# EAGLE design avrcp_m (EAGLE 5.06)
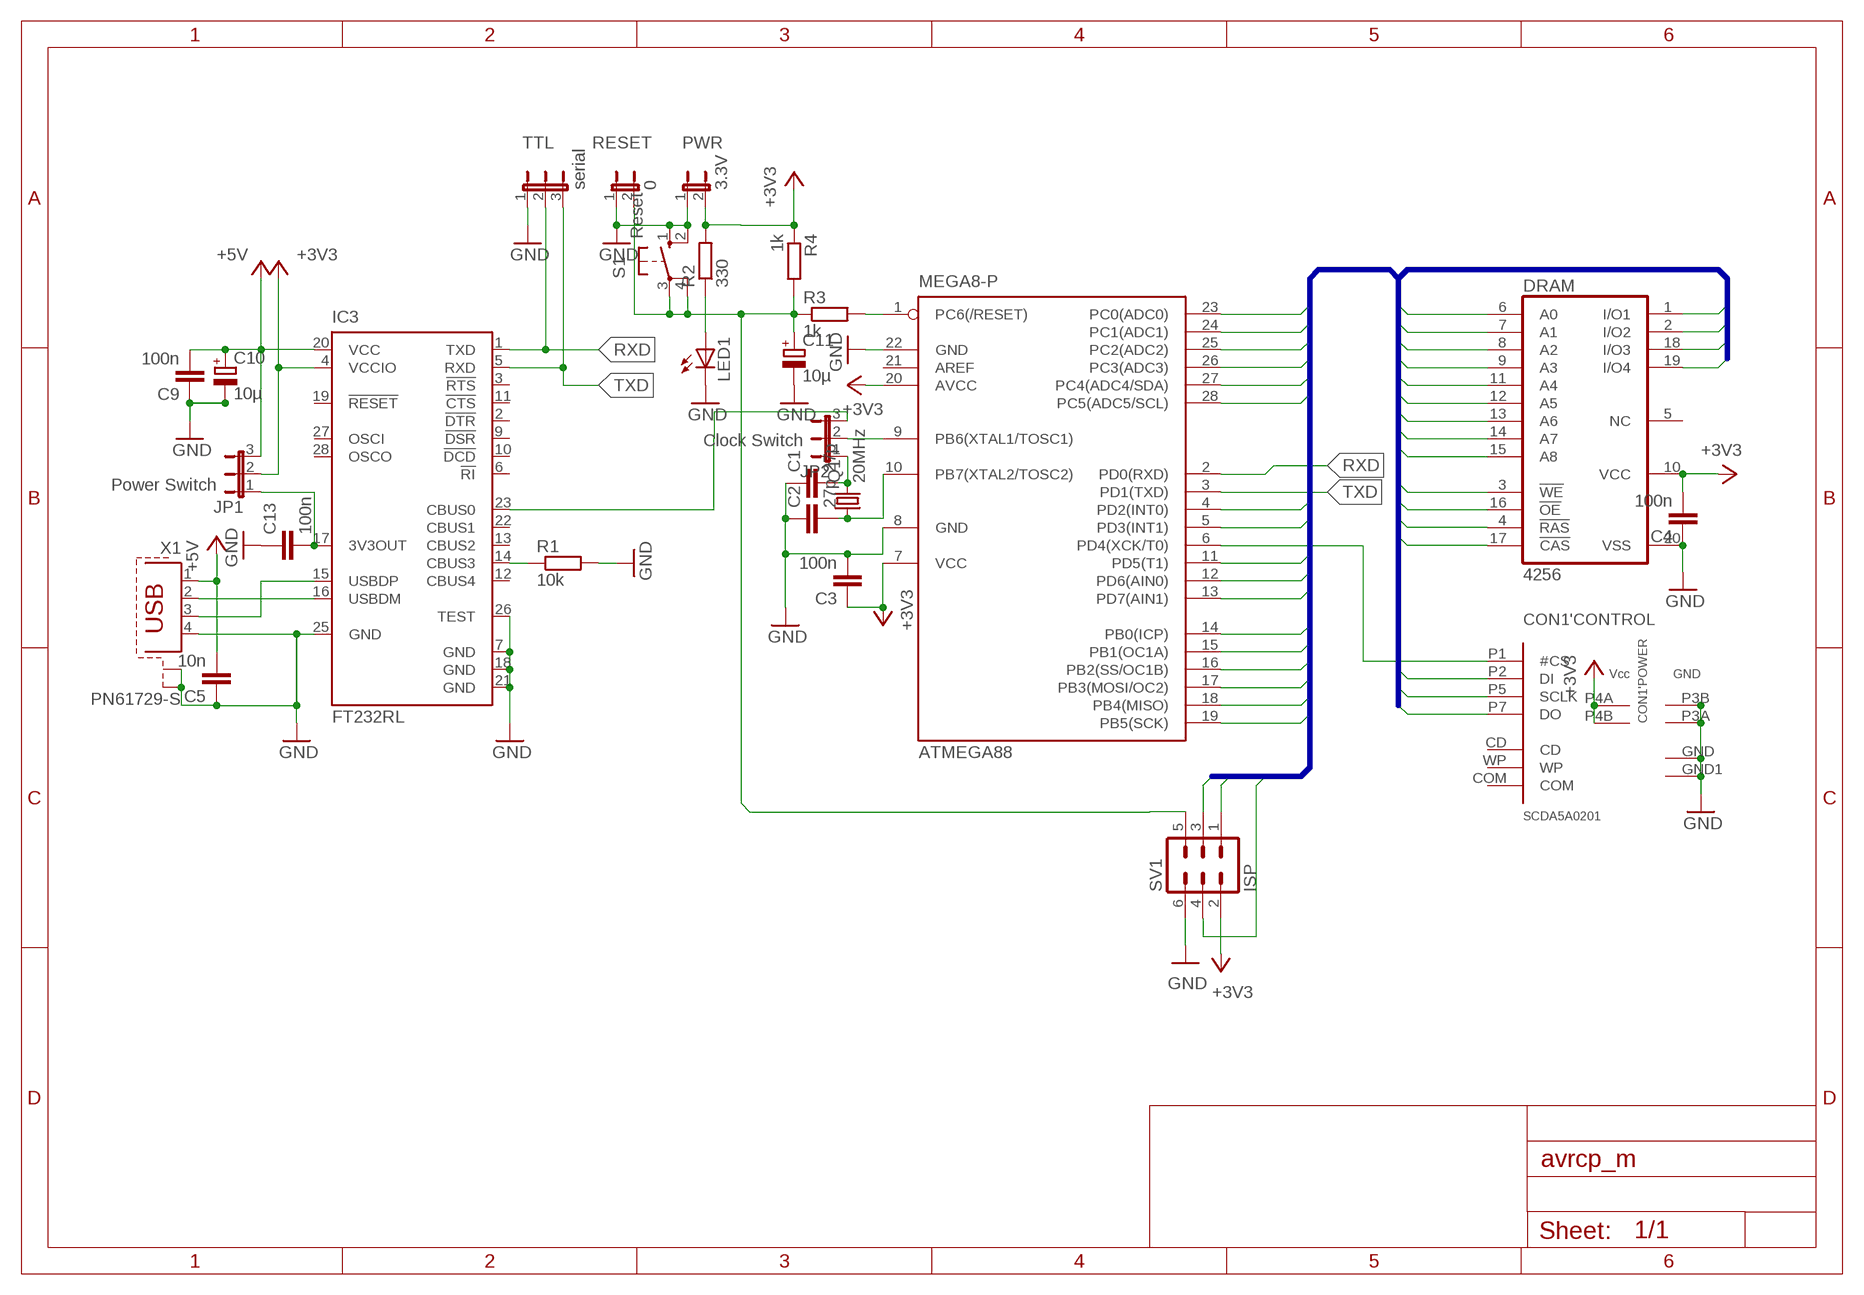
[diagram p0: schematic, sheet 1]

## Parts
ATMEGA88  MEGA8-P  [DIL28-3]
C1  27p  C-EU025-024X044  [C025-024X044]
C2  27p  C-EU025-024X044  [C025-024X044]
C3  100n  C-EU025-024X044  [C025-024X044]
C4  100n  C-EU025-024X044  [C025-024X044]
C5  10n  C-EU025-024X044  [C025-024X044]
C9  100n  C-EU025-024X044  [C025-024X044]
C10  10µ  CPOL-EUE2-5  [E2-5]
C11  10µ  CPOL-EUE2.5-5  [E2,5-5]
C13  100n  C-EU025-024X044  [C025-024X044]
CON1  SCDA5A0201  [SCDA5A0201]
DRAM  4256  514256ALP  [DIL20]
IC3  FT232RL  [SSOP28]
JP1  Power Switch  JP2E  [JP2]
JP2  Clock Switch  JP2E  [JP2]
LED1  LED3MM  [LED3MM]
PWR  3.3V  JP1E  [JP1]
Q1  20MHz  CRYSTALHC49U-V  [HC49U-V]
R1  10k  R-EU_0207/7  [0207/7]
R2  330  R-EU_0207/7  [0207/7]
R3  1k  R-EU_0207/7  [0207/7]
R4  1k  R-EU_0207/7  [0207/7]
RESET  0  JP1E  [JP1]
S1  Reset  10-XX  [B3F-10XX]
SV1  ISP  ML6  [ML6]
TTL  serial  JP2E  [JP2]
X1  PN61729-S  [PN61729-S]

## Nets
+3V3: ATMEGA88.7(VCC) ATMEGA88.20(AVCC) C3.1 C4.2 CON1.P4A('POWER:VCC) CON1.P4B('POWER:VCC1) DRAM.10(VCC) IC3.4(VCCIO) JP1.2 PWR.2 R2.2 R4.1 SV1.2
+5V: C5.2 C9.2 C10.+ IC3.20(VCC) JP1.3 X1.1
A0: ATMEGA88.18(PB4(MISO)) CON1.P7('CONTROL:DO) DRAM.6(A0) SV1.1
A1: ATMEGA88.17(PB3(MOSI/OC2)) CON1.P2('CONTROL:DI) DRAM.7(A1) SV1.4
A2: ATMEGA88.16(PB2(SS/OC1B)) DRAM.8(A2)
A3: ATMEGA88.15(PB1(OC1A)) DRAM.9(A3)
A4: ATMEGA88.14(PB0(ICP)) DRAM.11(A4)
A5: ATMEGA88.11(PD5(T1)) DRAM.12(A5)
A6: ATMEGA88.12(PD6(AIN0)) DRAM.13(A6)
A7: ATMEGA88.13(PD7(AIN1)) DRAM.14(A7)
A8: ATMEGA88.5(PD3(INT1)) DRAM.15(A8)
CAS: ATMEGA88.28(PC5(ADC5/SCL)) DRAM.17(!CAS)
CS: ATMEGA88.6(PD4(XCK/T0)) CON1.P1('CONTROL:#CS)
GND: ATMEGA88.8(GND) ATMEGA88.22(GND) C1.1 C2.1 C3.2 C4.1 C5.1 C9.1 C10.- C11.- C13.1 CON1.GND1('POWER:GND) CON1.GND('POWER:GND) CON1.P3A('POWER:GND) CON1.P3B('POWER:GND) DRAM.20(VSS) IC3.7(GND) IC3.18(GND) IC3.21(GND) IC3.25(GND) IC3.26(TEST) LED1.K(C) PWR.1 R1.2 RESET.1 S1.1(S) S1.2(S1) SV1.6 TTL.1 X1.4 X1.S1 X1.S2
IO1: ATMEGA88.23(PC0(ADC0)) DRAM.1(I/O1)
IO2: ATMEGA88.25(PC2(ADC2)) DRAM.2(I/O2)
IO3: ATMEGA88.27(PC4(ADC4/SDA)) DRAM.18(I/O3)
IO4: ATMEGA88.26(PC3(ADC3)) DRAM.19(I/O4)
N$1: IC3.14(CBUS3) R1.1
N$2: C13.2 IC3.17(3V3OUT) JP1.1
N$4: ATMEGA88.9(PB6(XTAL1/TOSC1)) JP2.2
N$5: ATMEGA88.10(PB7(XTAL2/TOSC2)) C2.2 Q1.1
N$6: C1.2 JP2.1 Q1.2
N$7: LED1.A R2.1
N$8: IC3.23(CBUS0) JP2.3
N$9: IC3.16(USBDM) X1.2
N$10: IC3.15(USBDP) X1.3
N$11: C11.+ R3.1 R4.2 RESET.2 S1.3(P) S1.4(P1) SV1.5
N$12: ATMEGA88.1(PC6(/RESET)) R3.2
OE: ATMEGA88.4(PD2(INT0)) DRAM.16(!OE)
RAS: ATMEGA88.19(PB5(SCK)) CON1.P5('CONTROL:SCLK) DRAM.4(!RAS) SV1.3
RXD: ATMEGA88.2(PD0(RXD)) IC3.1(TXD) TTL.2
TXD: ATMEGA88.3(PD1(TXD)) IC3.5(RXD) TTL.3
WE: ATMEGA88.24(PC1(ADC1)) DRAM.3(!WE)
Unconnected: ATMEGA88.21(AREF) CON1.CD('CONTROL:CD) CON1.COM('CONTROL:COM) CON1.WP('CONTROL:WP) DRAM.5(NC) IC3.2(!DTR) IC3.3(!RTS) IC3.6(!RI) IC3.9(!DSR) IC3.10(!DCD) IC3.11(!CTS) IC3.12(CBUS4) IC3.13(CBUS2) IC3.19(!RESET) IC3.22(CBUS1) IC3.27(OSCI) IC3.28(OSCO)

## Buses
A[0..8],WE,OE,RAS,CAS,IO[1..4]

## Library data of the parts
ATMEGA88 = atmel:MEGA8-P: MICROCONTROLLER 8 Kbytes FLASH, 1 kbytes SRAM, 512 bytes EEPROM, USART, 4-channel 10 bit ADC, 2-channel 8 bit ADC Pin compatible with Atmega48, ATMega88, ATMega168 Source: avr.lbr
C1-C5 C9 C13 = rcl:C-EU: CAPACITOR, European symbol
C10 C11 = rcl:CPOL-EU: POLARIZED CAPACITOR, European symbol
CON1 = SCDA5A0201:SCDA5A0201: ALPS Connector for SDMemory Card SD-CARD SCDA5A0201 SPI -MODE
DRAM = memory-hitachi:514256ALP: MEMORY
IC3 = ftdichip:FT232R: Source: http://www.ftdichip.com/Documents/DataSheets/DS_FT232R_v104.pdf
JP1 JP2 TTL = jumper:JP2E: JUMPER
LED1 = led:LED: LED
PWR RESET = jumper:JP1E: JUMPER
Q1 = crystal:CRYSTAL: CRYSTAL
R1-R4 = rcl:R-EU_: RESISTOR, European symbol
S1 = switch-omron:10-XX: OMRON SWITCH
SV1 = con-harting-ml:ML6: HARTING
X1 = con-berg:PN61729-S: BERG USB connector

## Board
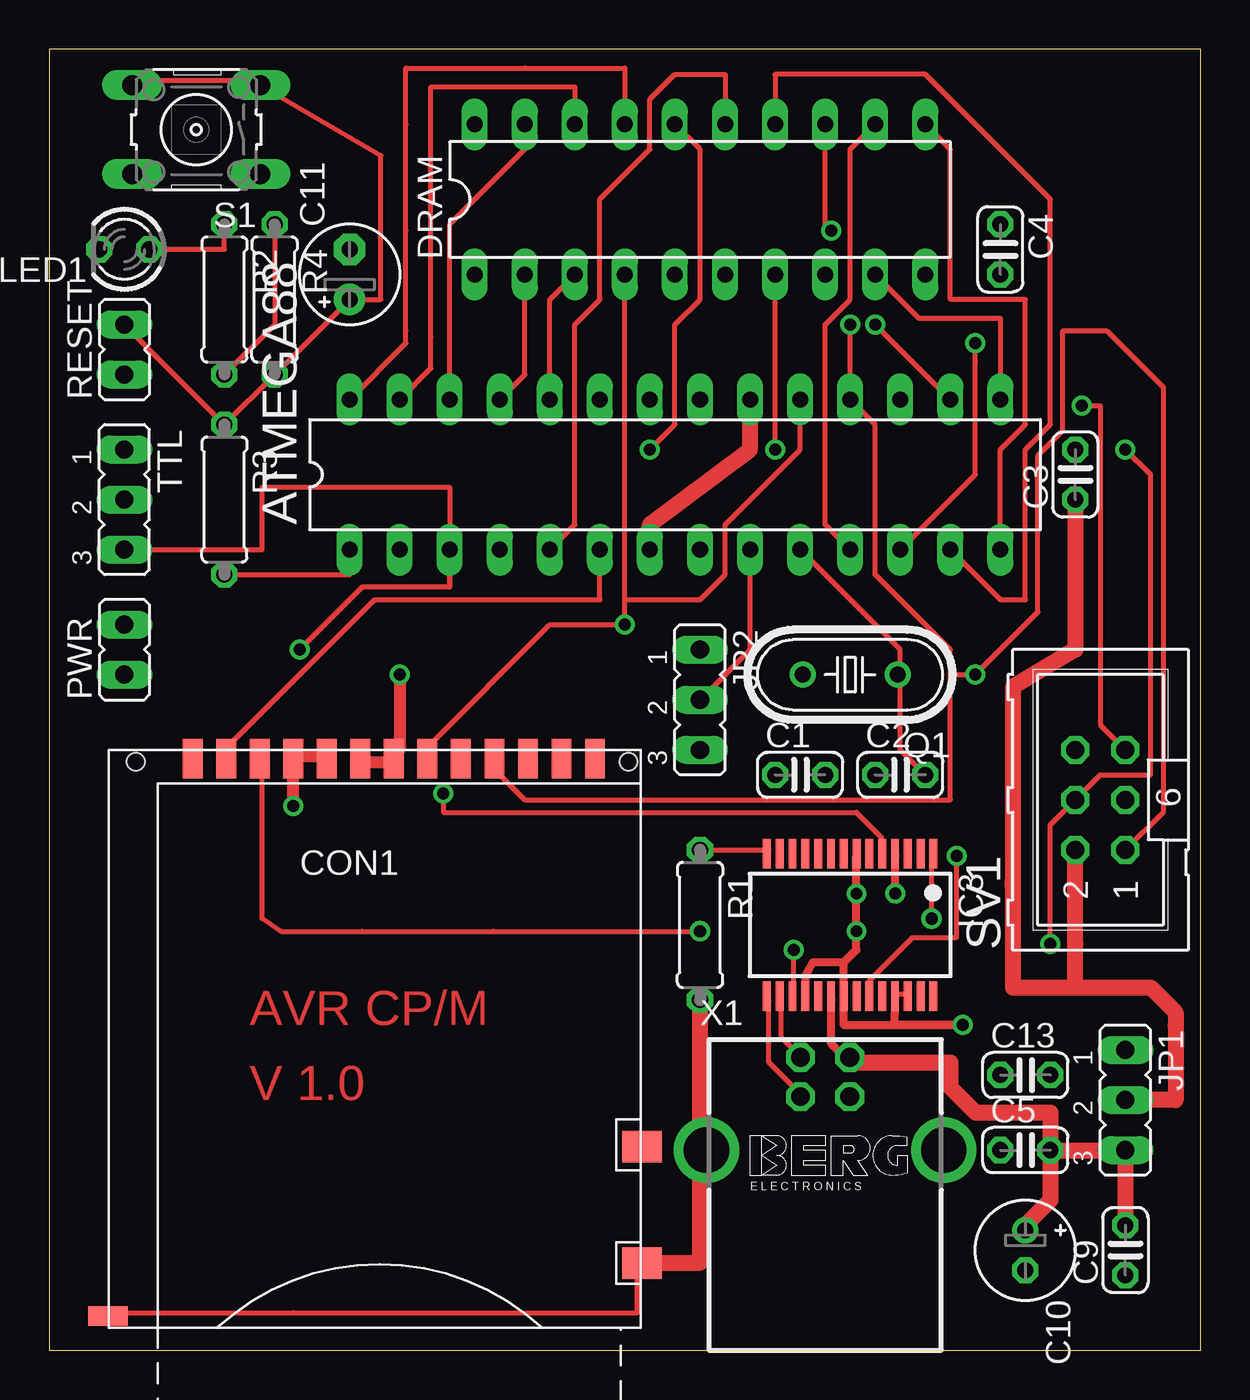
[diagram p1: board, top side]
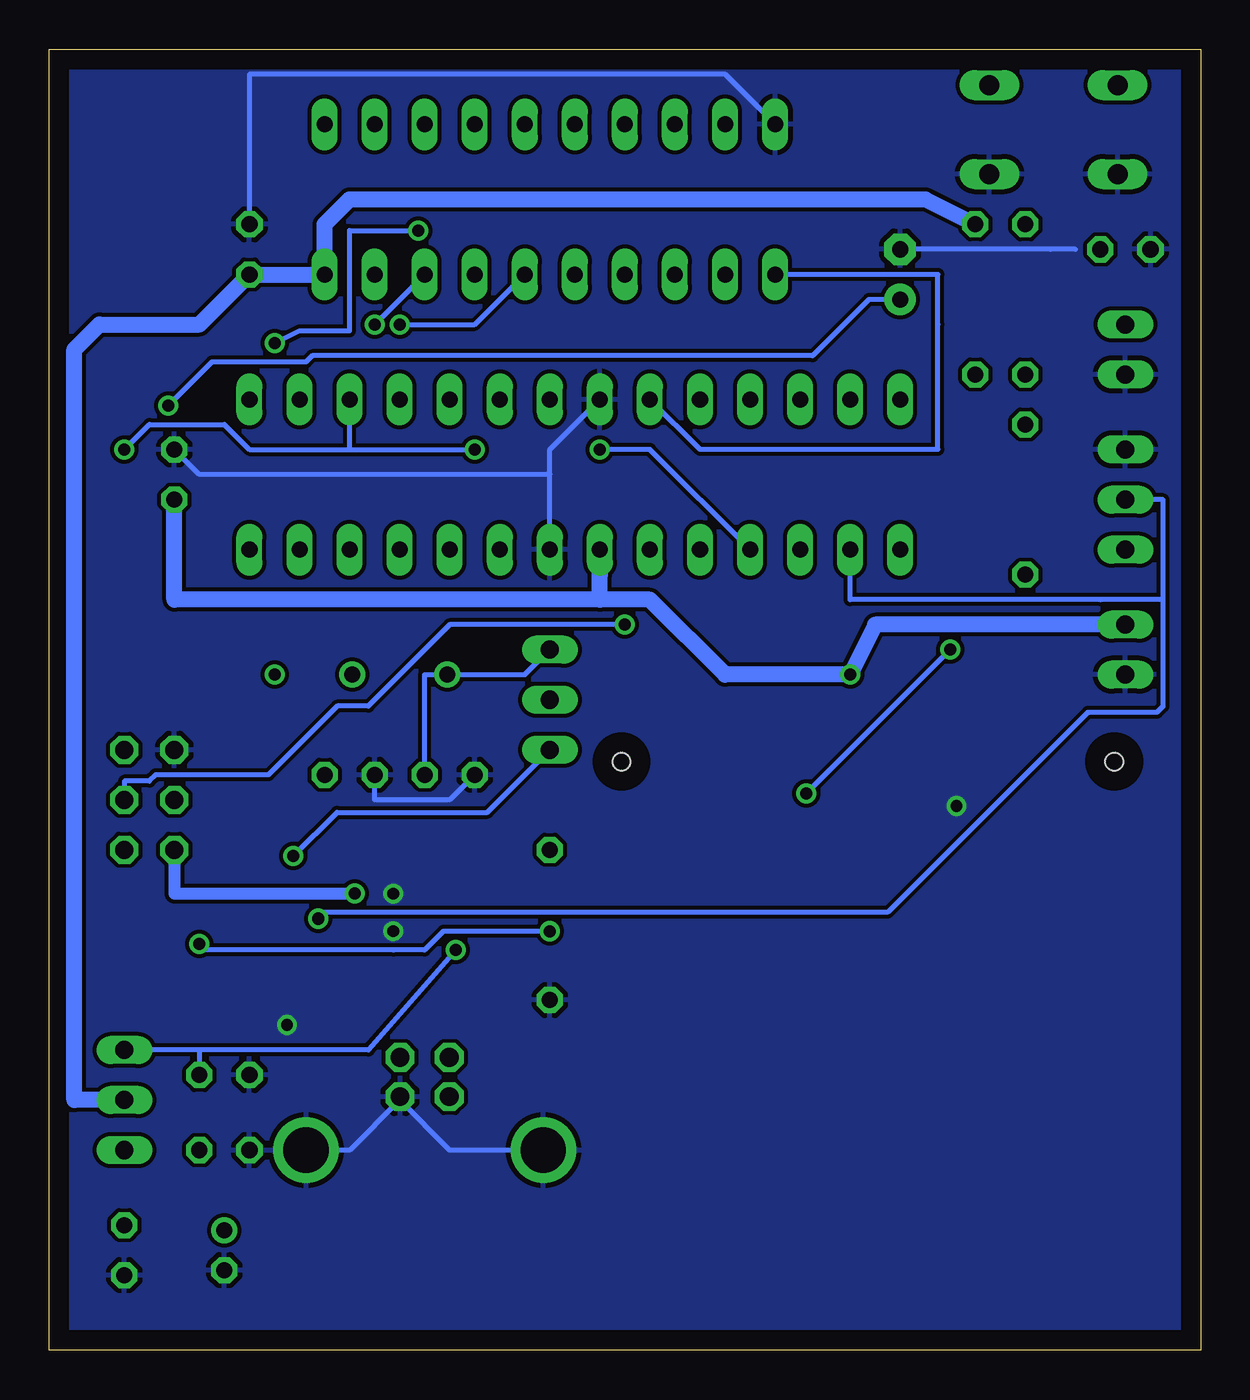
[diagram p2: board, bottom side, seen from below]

Size 58.42 x 66.04 mm. Coordinates in mm from the lower left corner, seen from the top.
Outline: 58.42,66.04 0,66.03 0,0 58.42,0 58.42,66.04
Copper layers (1*16): Top 0.035mm / dielectric 1.5mm / Bottom 0.035mm
Design rules "default": minimum track width 10mil, minimum drill 24mil, track to track 8mil, track to pad 8mil, pad to pad 8mil, via to via 8mil, smd to smd 8mil, copper to edge 40mil, drill to drill 8mil, minimum pad ring 10mil, minimum via ring 8mil, stop-mask expansion 4mil, vias tented up to drill 0mil, thermal gap 10mil

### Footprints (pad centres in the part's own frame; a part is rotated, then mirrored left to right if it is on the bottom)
DIL28-3 = drill 0.813 long: 1 -16.51,-3.81; 2 -13.97,-3.81; 3 -11.43,-3.81; 4 -8.89,-3.81; 5 -6.35,-3.81; 6 -3.81,-3.81; 7 -1.27,-3.81; 8 1.27,-3.81; 9 3.81,-3.81; 10 6.35,-3.81; 11 8.89,-3.81; 12 11.43,-3.81; 13 13.97,-3.81; 14 16.51,-3.81; 15 16.51,3.81; 16 13.97,3.81; 17 11.43,3.81; 18 8.89,3.81; 19 6.35,3.81; 20 3.81,3.81; 21 1.27,3.81; 22 -1.27,3.81; 23 -3.81,3.81; 24 -6.35,3.81; 25 -8.89,3.81; 26 -11.43,3.81; 27 -13.97,3.81; 28 -16.51,3.81
C025-024X044 = drill 0.813 octagon: 1 -1.27,0; 2 1.27,0
E2-5 = drill 0.813 pad 1.27 round: + -1.016,0 | drill 0.813 pad 1.27 octagon: - 1.016,0
E2,5-5 = drill 0.813 pad 1.6 round: + -1.27,0 | drill 0.813 pad 1.6 octagon: - 1.27,0
SCDA5A0201 = smd 1 x 2: CD 9.475,-0.45; COM 11.175,-0.45; P1 -7.525,-0.45; P2 -5.825,-0.45; P3A -4.125,-0.45; P3B -2.425,-0.45; P4A -0.725,-0.45; P4B 0.975,-0.45; P5 2.675,-0.45; P6 4.375,-0.45; P7 6.075,-0.45; P8 7.775,-0.45; P9 -9.225,-0.45 | smd 2 x 1.6: GND 13.575,-26.05; WP 13.575,-20.15 | smd 2 x 1: GND1 -13.525,-28.75 | hole 0.9: -12.125,-0.6; 12.875,-0.6
DIL20 = drill 0.813 long: 1 -11.43,-3.81; 2 -8.89,-3.81; 3 -6.35,-3.81; 4 -3.81,-3.81; 5 -1.27,-3.81; 6 1.27,-3.81; 7 3.81,-3.81; 8 6.35,-3.81; 9 8.89,-3.81; 10 11.43,-3.81; 11 11.43,3.81; 12 8.89,3.81; 13 6.35,3.81; 14 3.81,3.81; 15 1.27,3.81; 16 -1.27,3.81; 17 -3.81,3.81; 18 -6.35,3.81; 19 -8.89,3.81; 20 -11.43,3.81
SSOP28 = smd 0.4 x 1.5: 1 -4.225,-3.625; 2 -3.575,-3.625; 3 -2.925,-3.625; 4 -2.275,-3.625; 5 -1.625,-3.625; 6 -0.975,-3.625; 7 -0.325,-3.625; 8 0.325,-3.625; 9 0.975,-3.625; 10 1.625,-3.625; 11 2.275,-3.625; 12 2.925,-3.625; 13 3.575,-3.625; 14 4.225,-3.625; 15 4.225,3.625; 16 3.575,3.625; 17 2.925,3.625; 18 2.275,3.625; 19 1.625,3.625; 20 0.975,3.625; 21 0.325,3.625; 22 -0.325,3.625; 23 -0.975,3.625; 24 -1.625,3.625; 25 -2.275,3.625; 26 -2.925,3.625; 27 -3.575,3.625; 28 -4.225,3.625
JP2 = drill 0.914 long: 1 -2.54,0; 2 0,0; 3 2.54,0
LED3MM = drill 0.813 octagon: A -1.27,0; K 1.27,0
JP1 = drill 0.914 long: 1 0,-1.27; 2 0,1.27
HC49U-V = drill 0.813 round: 1 -2.413,0; 2 2.413,0
0207/7 = drill 0.813 octagon: 1 -3.81,0; 2 3.81,0
B3F-10XX = drill 1.016 long: 1 -3.251,2.261; 2 3.251,2.261; 3 -3.251,-2.261; 4 3.251,-2.261
ML6 = drill 0.914 octagon: 1 -2.54,-1.27; 2 -2.54,1.27; 3 0,-1.27; 4 0,1.27; 5 2.54,-1.27; 6 2.54,1.27
PN61729-S = drill 0.95 octagon: 1 1.25,4.71; 2 -1.25,4.71; 3 -1.25,2.71; 4 1.25,2.71 | drill 2.3 pad 2.9 round: S1 -6.02,0; S2 6.02,0

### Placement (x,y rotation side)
ATMEGA88  31.75,44.45 0 top
C1  38.1,29.21 0 top
C2  43.18,29.21 0 top
C3  52.07,44.45 90 top
C4  48.26,55.88 270 top
C5  49.53,10.16 0 top
C9  54.61,5.08 90 top
C10  49.53,5.08 270 top
C11  15.24,54.61 90 top
C13  49.53,13.97 0 top
CON1  16.51,30.48 0 top
DRAM  33.02,58.42 0 top
IC3  40.64,21.59 180 top
JP1  54.61,12.7 270 top
JP2  33.02,33.02 270 top
LED1  3.81,55.88 180 top
PWR  3.81,35.56 0 top
Q1  40.64,34.29 180 top
R1  33.02,21.59 270 top
R2  8.89,53.34 270 top
R3  8.89,43.18 270 top
R4  11.43,53.34 270 top
RESET  3.81,50.8 0 top
S1  7.46,61.96 180 top
SV1  53.34,27.94 90 top
TTL  3.81,43.18 270 top
X1  39.37,10.16 0 top

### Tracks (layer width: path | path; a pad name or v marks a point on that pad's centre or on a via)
+3V3  (via drill 0.61)
  Top 0.254: 17.78,30.48 CON1.P4B 17.14,29.84 | 15.88,29.84 CON1.P4A | 42.93,25.08 IC3.4 | 48.9,23.5 48.9,23.81 | R2.2 11.43,52.07 R4.1
  Top 0.406: v42.93,23.18 42.93,25.08
  Top 0.61: v17.78,34.29 17.78,30.48 | 17.14,29.84 15.88,29.84
  Top 0.813: C3.1 52.07,35.56 48.9,33.66 48.9,23.5 | JP1.2 57.15,12.7 57.15,16.51 57.15,17.14 55.88,18.41 52.07,18.41 | ATMEGA88.7 30.48,41.91 35.56,45.72 ATMEGA88.20 | SV1.2 52.07,20.64 52.07,18.41 | 48.9,23.5 48.9,23.81 | 48.9,23.5 48.9,18.41 52.07,18.41
  Bottom 0.61: v42.93,23.18 52.07,23.18 SV1.2
  Bottom 0.813: PWR.2 16.51,36.83 v17.78,34.29 24.13,34.29 27.94,38.1 | 27.94,38.1 30.48,38.1 30.48,39.37 ATMEGA88.7 | C3.1 52.07,38.1 27.94,38.1 | JP1.2 57.15,12.7 57.15,50.8 55.88,52.07 50.8,52.07 C4.2 DRAM.10 44.45,57.15 43.18,58.42 40.64,58.42 15.88,58.42 13.97,58.42 R4.1
+5V
  Top 0.254: 49.53,6.35 C10.+ | 39.69,17.78 IC3.20 | X1.1 40.32,14.92
  Top 0.406: 39.69,17.78 39.69,15.56 40.32,14.92
  Top 0.813: C9.2 JP1.3 C5.2 | 49.53,6.35 50.8,7.62 C5.2 | C5.2 50.8,12.06 47.62,12.06 46.99,12.06 45.72,13.34 45.72,14.61 40.88,14.61 X1.1
A0  (via drill 0.61)
  Top 0.254: 45.72,34.29 45.72,35.56 41.91,39.37 41.91,46.99 ATMEGA88.18 v40.64,52.07 | 45.72,34.29 45.72,27.94 24.13,27.94 22.86,29.21 CON1.P7 | 45.72,34.29 v46.99,34.29 50.16,37.47 50.16,45.4 51.44,46.67 51.44,51.75 53.66,51.75 56.52,48.9 56.52,27.3 SV1.1
  Bottom 0.254: DRAM.6 36.83,52.07 v40.64,52.07
A1  (via drill 0.61)
  Top 0.254: v36.83,45.72 DRAM.7 | v54.61,45.72 55.88,44.45 55.88,29.21 53.34,29.21 SV1.4 50.8,26.67 v50.8,20.64 | 10.79,30.48 10.79,30.16 CON1.P2 | 10.79,30.48 10.79,30.8 10.79,30.48 | 10.79,30.48 10.79,21.91 11.75,21.27 15.88,21.27 22.54,21.27 v33.02,21.27
  Bottom 0.254: 43.18,45.72 v36.83,45.72 | 43.18,45.72 ATMEGA88.17 | v54.61,45.72 53.34,46.99 49.53,46.99 48.26,45.72 43.18,45.72 | v33.02,21.27 38.42,21.27 39.37,20.32 40.96,20.32 50.8,20.32 v50.8,20.64
A2  (via drill 0.61)
  Top 0.254: v41.91,52.07 ATMEGA88.16
  Bottom 0.254: DRAM.8 v41.91,52.07
A3
  Top 0.254: DRAM.9 44.13,52.39 46.67,52.39 48.26,52.39 ATMEGA88.15
A4
  Top 0.254: ATMEGA88.14 48.26,45.72 49.53,46.99 49.53,53.34 45.72,53.34 45.72,60.96 DRAM.11
A5
  Top 0.254: ATMEGA88.11 39.37,41.91 39.37,52.07 40.64,53.34 40.64,60.96 DRAM.12
A6  (via drill 0.61)
  Top 0.254: ATMEGA88.12 46.99,44.45 46.99,50.16 v46.99,51.12 | v39.69,56.83 39.37,57.15 DRAM.13
  Bottom 0.254: v46.99,51.12 45.72,51.75 45.09,51.75 43.18,51.75 43.18,56.83 v39.69,56.83
A7
  Top 0.254: ATMEGA88.13 48.26,38.1 49.53,38.1 49.53,45.72 50.8,46.99 50.8,58.42 44.45,64.77 36.83,64.77 DRAM.14
A8
  Top 0.254: ATMEGA88.5 26.67,41.91 26.67,52.07 27.94,53.34 27.94,58.42 30.48,60.96 30.48,63.5 31.75,64.77 34.29,64.77 DRAM.15
CAS
  Top 0.254: DRAM.17 29.21,65.09 24.13,65.09 18.1,65.09 18.1,62.23 18.1,56.83 18.1,51.75 18.1,51.12 ATMEGA88.28
CS
  Top 0.254: ATMEGA88.6 27.94,38.1 16.51,38.1 8.89,30.48 CON1.P1
GND  (via drill 0.6)
  Top 0.254: IC3.26 43.5,18.1 42.86,18.1 IC3.25 42.86,17.78 42.91,17.14 | 38.37,18.09 IC3.18 | 40.32,18.1 IC3.21 40.32,17.78 | 40.96,25.08 IC3.7 | CON1.GND1 3.17,1.91 12.38,1.91 29.84,1.91 29.84,4.13 CON1.GND | 13.97,30.16 CON1.P3B | CON1.P3A 12.7,30.16 | C10.- 49.53,3.81 C10.- | 33.02,10.16 X1.S1 33.02,10.16
  Top 0.406: 38.37,18.09 38.37,19.04 38.73,19.68 40.32,19.68 | 40.32,18.1 40.32,19.68 | 40.96,25.08 v40.96,23.18 v40.96,21.27 40.96,20.32 40.32,19.68 | 42.91,17.14 42.91,16.51 v46.35,16.51 40.32,16.51 40.32,17.78
  Top 0.61: v12.38,27.62 CON1.P3A | 12.7,30.16 13.97,30.16
  Top 0.813: R1.2 33.02,10.16 33.02,6.99 33.02,4.45 CON1.GND
  Bottom 0.254: C11.- 7.62,55.88 6.35,55.88 | C1.1 38.1,27.94 41.91,27.94 C2.1 | 33.02,44.45 33.02,45.72 ATMEGA88.22 | ATMEGA88.8 33.02,44.45 | 33.02,44.45 50.8,44.45 C3.2 | 40.64,12.7 43.18,10.16 44.45,10.16 X1.S2 | 40.64,12.7 X1.4 40.64,12.7 | 40.64,12.7 38.1,10.16 34.29,10.16 X1.S1 | C4.1 48.26,64.77 24.13,64.77 DRAM.20
  pour Bottom: 0,66.04 58.42,66.04 58.42,0 0,0
IO1
  Bottom 0.254: DRAM.1 13.34,54.61 13.34,52.07 13.34,45.72 25.4,45.72 ATMEGA88.23
IO2
  Top 0.254: ATMEGA88.25 24.13,49.53 DRAM.2
IO3
  Top 0.254: DRAM.18 26.67,64.14 19.37,64.14 19.37,51.44 19.37,49.85 ATMEGA88.27
IO4
  Top 0.254: ATMEGA88.26 20.32,57.15 24.13,60.96 DRAM.19
N$1
  Top 0.254: R1.1 36.51,25.4 IC3.14
N$2  (via drill 0.61)
  Top 0.254: v37.78,20.32 37.78,18.1 IC3.17
  Bottom 0.254: 50.8,15.24 C13.2 | 50.8,15.24 JP1.1 | v37.78,20.32 42.23,15.24 50.8,15.24
N$4
  Top 0.254: ATMEGA88.9 35.56,35.56 JP2.2
N$5
  Top 0.254: C2.2 43.18,30.48 43.18,34.29 | 43.18,34.29 Q1.1 43.18,34.29 | ATMEGA88.10 43.18,35.56 43.18,34.29
N$6
  Bottom 0.254: C1.2 39.37,34.29 Q1.2 | Q1.2 38.1,34.29 | Q1.2 38.1,34.29 | JP2.1 34.29,34.29 38.1,34.29 | Q1.2 38.1,34.29
N$7
  Top 0.254: LED1.A 8.89,55.88 R2.1
N$8  (via drill 0.61)
  Top 0.254: v46.04,25.08 46.04,20.95 43.81,20.95 41.59,18.73 41.59,18.1 IC3.23
  Bottom 0.254: v46.04,25.08 43.81,27.3 36.2,27.3 JP2.3
N$9
  Top 0.254: IC3.16 37.15,17.78 37.15,15.88 38.1,14.92 X1.2
N$10
  Top 0.254: IC3.15 36.51,17.78 36.51,14.61 38.1,13.02 X1.3
N$11  (via drill 0.61)
  Top 0.254: RESET.2 R3.1 R4.2 C11.+ 16.83,53.34 16.83,60.64 10.79,64.14 S1.3 10.48,64.45 4.45,64.45 S1.4 | SV1.5 53.34,31.75 53.34,47.94 v52.39,47.94
  Bottom 0.254: v52.39,47.94 50.16,50.16 45.4,50.16 45.09,50.48 19.68,50.48 16.83,53.34 C11.+
N$12
  Top 0.254: R3.2 15.24,39.37 ATMEGA88.1
OE  (via drill 0.61)
  Top 0.254: v30.48,45.72 31.75,46.99 31.75,52.07 33.02,53.34 33.02,60.96 DRAM.16
  Bottom 0.254: ATMEGA88.4 27.94,45.72 v30.48,45.72
RAS  (via drill 0.61)
  Top 0.254: 29.21,38.1 DRAM.4 | 29.21,38.1 v29.21,36.83 25.4,36.83 19.05,30.48 CON1.P5 | ATMEGA88.19 38.1,45.72 34.29,41.91 34.29,39.37 33.02,38.1 29.21,38.1
  Bottom 0.254: v29.21,36.83 38.1,36.83 42.23,32.7 43.81,32.7 47.31,29.21 53.02,29.21 53.34,28.89 54.61,28.89 SV1.3
RXD  (via drill 0.61)
  Top 0.254: v44.77,21.91 44.77,25.08 IC3.1
  Bottom 0.254: ATMEGA88.2 17.78,38.1 5.08,38.1 1.91,38.1 | 1.91,37.47 1.91,38.1 | 1.91,37.47 1.91,38.1 | 1.91,38.1 1.91,43.18 TTL.2 | v44.77,21.91 44.45,22.23 15.88,22.23 5.71,32.38 5.08,32.38 2.22,32.38 1.91,32.7 1.91,37.47 | 1.91,37.47 1.91,38.1
TXD  (via drill 0.61)
  Top 0.254: IC3.5 42.23,25.4 42.23,26.04 40.96,27.3 20,27.3 v20,28.26 | v12.7,35.56 15.88,38.73 20.32,38.73 | 20.32,38.73 ATMEGA88.3 | 10.79,43.5 10.79,43.81 | 10.79,43.81 20.32,43.81 20.32,38.73 | TTL.3 10.79,40.64 10.79,43.5 | 10.79,43.5 10.79,43.81
  Bottom 0.254: v12.7,35.56 v20,28.26
WE
  Top 0.254: ATMEGA88.24 25.4,53.34 DRAM.3

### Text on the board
Top: AVR CP/M | V 1.0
